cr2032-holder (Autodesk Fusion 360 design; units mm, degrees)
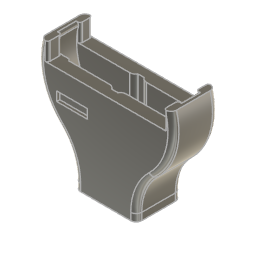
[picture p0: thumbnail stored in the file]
parameter "battery_diameter" = 20
parameter "battery_height" = 3.2
parameter "battery_negative_diameter" = 16
parameter "battery_negative_height" = 0.3
parameter "battery_tolerance" = 0.1
parameter "connector_width" = 2.9
parameter "connector_pin" = 1
parameter "holder_thickness_h" = 2
parameter "holder_thickness_w" = 2.05
parameter "pin_holder_distance" = 3
parameter "holder_clip" = 3
sketch "Sketch1" plane through (0, 0, 0) normal (0, 0, 1) x axis (1, 0, 0)
  line L1 (11.0748, -0.0744) -> (-11.0748, -0.0744)
  circle C1 centre (0, 0) radius 11.075
  circle C2 centre (0, 0) radius 10.05
  point P1 (0, 0)
  point P2 (0, 0)
  point P3 (0, 0)
  point P4 (-11.0748, -0.0744)
  point P5 (11.0748, -0.0744)
  coincident P1 P2
  coincident P1 P3
  coincident C1 P4
  coincident C1 P5
  horizontal L1
  dimension "d9" diameter C1 = 22.15 (= "battery_diameter + battery_tolerance + holder_thickness_w")
  dimension "d10" diameter C2 = 20.1 (= "battery_diameter + battery_tolerance")
extrude "Extrude1" new body sketch "Sketch1" no distance stored
extrude "Extrude2" add sketch "Sketch1" along normal blind 3.3 (= "battery_height + battery_tolerance")
sketch "Sketch2" plane through (0, 0, 3.3) normal (0, 0, 1) x axis (-1, 0, 0)
  line L1 (-10.0497, 0.0744) -> (-11.0748, 0.0744)
  line L2 (11.0748, 0.0744) -> (10.0497, 0.0744)
  line L3 (-11.0748, 0.0744) -> (11.0748, 0.0744)
  arc A1 centre (0, 0) radius 11.075 clockwise from (-11.0748, 0.0744) to (11.0748, 0.0744)
  arc A2 centre (0, 0) radius 10.05 clockwise from (-10.0497, 0.0744) to (10.0497, 0.0744)
  circle C1 centre (0, 0) radius 11.075
  point P2 (11.0748, 0.0744)
  point P8 (11.0748, 0.0744)
  point P3 (-11.0748, 0.0744)
  point P9 (-11.0748, 0.0744)
  concentric A1 C1
  coincident P2 P8
  coincident P3 P9
  dimension "d16" diameter C1 = 22.15 (= "battery_diameter + battery_tolerance + holder_thickness_w")
extrude "Extrude3" add sketch "Sketch2" along normal blind 2 (= "holder_thickness_h")
offset_faces "OffsetFaces1" distance 3 (= "holder_clip")
sketch "Sketch12" plane through (0, 0, 5.3) normal (0, 0, 1) x axis (-1, 0, 0)
  line L1 (10.6816, -2.9256) -> (-10.6816, -2.9256)
  line L2 (0, -5) -> (0, 0)
  line L3 (-9.5, 0) -> (0, 0)
  line L4 (-9.5, -3) -> (-9.5, 0)
  line L5 (0, -3) -> (-9.5, -3)
  line L6 (0, 0) -> (0, -3)
  line L7 (0, -3) -> (9.5, -3)
  line L8 (9.5, 0) -> (0, 0)
  line L9 (9.5, -3) -> (9.5, 0)
  arc A1 centre (0, 0) radius 11.075 clockwise from (-10.6816, -2.9256) to (10.6816, -2.9256)
  point P1 (0, 0)
  point P5 (0, 0)
  point P7 (0, 0)
  point P13 (0, 0)
  point P8 (-9.5, 0)
  point P14 (9.5, 0)
  point P9 (-9.5, -3)
  point P11 (9.5, -3)
  point P10 (0, -3)
  point P12 (0, -3)
  coincident P1 P5
  perpendicular L1 L2
  horizontal L3
  vertical L4
  horizontal L5
  vertical L6
  coincident P1 P7
  symmetric L2 P7 P13
  symmetric L2 P8 P14
  symmetric L2 P9 P11
  symmetric L2 P10 P12
  dimension "d112" distance P7 P8 = 9.5 (= "( battery_diameter / 2 ) - 0.5 mm")
  dimension "d113" distance P7 P10 = 3 (= "holder_clip")
extrude "Extrude15" cut sketch "Sketch12" profile of L1 L2 L3 L4 L6 L8 L9 to an object
sketch "Sketch3" plane through (0, 0, 5.3) normal (0, 0, 1) x axis (-1, 0, 0)
  line L1 (10.6816, -2.9256) -> (9.5, -2.9256)
  line L2 (5, 12.575) -> (-5, 12.575)
  line L3 (5, 9.575) -> (5, 12.575)
  line L4 (-5, 9.575) -> (5, 9.575)
  line L5 (-5, 12.575) -> (-5, 9.575)
  line L6 (5, 9.575) -> (-5, 12.575)
  line L7 (-5, 9.575) -> (5, 12.575)
  line L8 (-9.5, 0) -> (-9.5, -2.9256)
  line L9 (9.5, 0) -> (-9.5, 0)
  line L10 (9.5, -2.9256) -> (9.5, 0)
  line L11 (-9.5, -2.9256) -> (-10.6816, -2.9256)
  arc A1 centre (0, 0) radius 11.075 clockwise from (-10.6816, -2.9256) to (10.6816, -2.9256)
  point P9 (0, 11.075)
  point P7 (5, 9.575)
  point P8 (-5, 9.575)
  point P6 (5, 12.575)
  horizontal L2
  perpendicular L2 L3
  parallel L2 L4
  parallel L3 L5
  coincident L6 P9
  coincident L7 P9
  midpoint A1 P9
  dimension "d19" distance P7 P8 = 10
  dimension "d20" distance P6 P7 = 3
extrude "Extrude4" add sketch "Sketch3" profile of A1 L2 L3 L5 to an object
sketch "Sketch4" plane through (0, -12.575, 0) normal (0, -1, 0) x axis (1, 0, 0)
  line L1 (5, -2) -> (-5, -2)
  line L2 (5, 5.3) -> (5, -2)
  line L3 (-5, 5.3) -> (5, 5.3)
  line L4 (-5, -2) -> (-5, 5.3)
  line L5 (-1.4556, 1.85) -> (1.4444, 1.85)
  line L6 (-1.4556, 4.75) -> (-1.4556, 1.85)
  line L7 (1.4444, 4.75) -> (-1.4556, 4.75)
  line L8 (1.4444, 1.85) -> (1.4444, 4.75)
  line L9 (-1.4556, 4.75) -> (1.4444, 1.85)
  line L10 (1.4444, 4.75) -> (-1.4556, 1.85)
  line L11 (-1.4556, -1.45) -> (1.4444, -1.45)
  line L12 (-1.4556, 1.45) -> (-1.4556, -1.45)
  line L13 (1.4444, 1.45) -> (-1.4556, 1.45)
  line L14 (1.4444, -1.45) -> (1.4444, 1.45)
  line L15 (-1.4556, 1.45) -> (1.4444, -1.45)
  line L16 (1.4444, 1.45) -> (-1.4556, -1.45)
  point P10 (-0.0056, 3.3)
  point P15 (-0.0056, 0)
  point P8 (-1.4556, 4.75)
  point P9 (1.4444, 4.75)
  point P7 (-1.4556, 1.85)
  point P13 (-1.4556, 1.45)
  point P14 (1.4444, 1.45)
  point P12 (-1.4556, -1.45)
  horizontal L5
  perpendicular L5 L6
  parallel L5 L7
  parallel L6 L8
  coincident L9 P10
  coincident L10 P10
  horizontal L11
  perpendicular L11 L12
  parallel L11 L13
  parallel L12 L14
  coincident L15 P15
  coincident L16 P15
  dimension "d23" distance P8 P9 = 2.9 (= "connector_width")
  dimension "d24" distance P7 P8 = 2.9 (= "connector_width")
  dimension "d25" distance L3 P10 = 2 (= "holder_thickness_h")
  dimension "d26" distance P13 P14 = 2.9 (= "connector_width")
  dimension "d27" distance P12 P13 = 2.9 (= "connector_width")
  dimension "d28" distance L1 P15 = 2 (= "holder_thickness_h")
extrude "Extrude5" cut sketch "Sketch4" profile of L5 L6 L7 L8 L11 L12 L13 L14 to an object
sketch "Sketch5" plane through (0, 0, 0) normal (0, 0, 1) x axis (-1, 0, 0)
  line L1 (9.6147, -2.9256) -> (9.5, -2.9256)
  line L2 (0.5056, 10.05) -> (0.0056, 10.05)
  line L3 (0.5056, -2.25) -> (0.5056, 10.05)
  line L4 (0.0056, -2.25) -> (0.5056, -2.25)
  line L5 (0.0056, 10.05) -> (0.0056, -2.25)
  line L6 (-0.4944, 10.05) -> (0.0056, 10.05)
  line L7 (-0.4944, -2.25) -> (-0.4944, 10.05)
  line L8 (0.0056, -2.25) -> (-0.4944, -2.25)
  line L9 (0.0056, 10.05) -> (0.0056, -2.25)
  line L10 (9.5, -2.9256) -> (9.5, 0)
  line L11 (-9.5, -2.9256) -> (-9.6147, -2.9256)
  line L12 (-9.5, 0) -> (-9.5, -2.9256)
  line L13 (9.5, 0) -> (-9.5, 0)
  arc A1 centre (0, 0) radius 10.05 clockwise from (1.4556, 9.944) to (9.6147, -2.9256)
  arc A2 centre (0, 0) radius 10.05 clockwise from (-1.4444, 9.9457) to (1.4556, 9.944)
  arc A3 centre (0, 0) radius 10.05 clockwise from (-9.6147, -2.9256) to (-1.4444, 9.9457)
  point P7 (0.0056, 10.05)
  point P8 (0.5056, 10.05)
  horizontal L2
  vertical L3
  horizontal L4
  vertical L5
  midpoint A2 P7
  horizontal L6
  vertical L7
  horizontal L8
  vertical L9
  dimension "d31" distance P7 P8 = 0.5 (= "connector_pin / 2")
extrude "Extrude6" cut sketch "Sketch5" profile of A2 L1 L3 L5 L7 L9 against normal blind 0.5 (magnitude of "-connector_pin / 2")
sketch "Sketch6" plane through (0, 0, 3.3) normal (0, 0, -1) x axis (1, 0, 0)
  line L1 (9.6147, -2.9256) -> (9.5, -2.9256)
  line L2 (-0.5056, 10.05) -> (-0.0056, 10.05)
  line L3 (-0.5056, -2.3823) -> (-0.5056, 10.05)
  line L4 (-0.0056, -2.3823) -> (-0.5056, -2.3823)
  line L5 (-0.0056, 10.05) -> (-0.0056, -2.3823)
  line L6 (0.4944, 10.05) -> (-0.0056, 10.05)
  line L7 (0.4944, -2.3823) -> (0.4944, 10.05)
  line L8 (-0.0056, -2.3823) -> (0.4944, -2.3823)
  line L9 (-0.0056, 10.05) -> (-0.0056, -2.3823)
  line L10 (9.5, -2.9256) -> (9.5, 0)
  line L11 (-9.5, -2.9256) -> (-9.6147, -2.9256)
  line L12 (-9.5, 0) -> (-9.5, -2.9256)
  line L13 (9.5, 0) -> (-9.5, 0)
  arc A1 centre (0, 0) radius 10.05 clockwise from (1.4444, 9.9457) to (9.6147, -2.9256)
  arc A2 centre (0, 0) radius 10.05 clockwise from (-1.4556, 9.944) to (1.4444, 9.9457)
  arc A3 centre (0, 0) radius 10.05 clockwise from (-9.6147, -2.9256) to (-1.4556, 9.944)
  circle C1 centre (0, 0) radius 8.05
  point P1 (0, 0)
  point P7 (0, 0)
  point P8 (-0.0056, 10.05)
  point P9 (-0.5056, 10.05)
  coincident P1 P7
  horizontal L2
  vertical L3
  horizontal L4
  vertical L5
  midpoint A2 P8
  horizontal L6
  vertical L7
  horizontal L8
  vertical L9
  dimension "d34" diameter C1 = 16.1 (= "battery_negative_diameter + battery_tolerance")
  dimension "d35" distance P8 P9 = 0.5 (= "connector_pin / 2")
extrude "Extrude14" add sketch "Sketch6" profile of A1 A2 A3 L1 C1 L3 L7 along normal blind 0.3 (= "battery_negative_height")
extrude "Extrude8" cut sketch "Sketch6" profile of A2 L1 C1 L3 L4 L5 L7 L8 L9 against normal blind 0.5 (magnitude of "-connector_pin / 2")
fillet "Fillet7" radius 1 (= "connector_pin") 1 (= "connector_pin")
extrude "Extrude11" add of existing geometry blind 3 (= "pin_holder_distance")
fillet "Fillet10" radius 9 (= "pin_holder_distance * 3")
fillet "Fillet11" radius 0.7
fillet "Fillet16" radius 1.5
fillet "Fillet17" radius 1.25
fillet "Fillet18" radius 1.5
sketch "Sketch13" plane through (0, 0, -2) normal (0, 0, -1) x axis (1, 0, 0)
  line L1 (-9.5, 0) -> (-9.5, -2.9256)
  line L2 (9.5, 0) -> (-9.5, 0)
  line L3 (9.5, -2.9256) -> (9.5, 0)
  line L4 (10.6816, -2.9256) -> (9.5, -2.9256)
  line L5 (5, 15.575) -> (5, 14.3877)
  line L6 (-5, 15.575) -> (5, 15.575)
  line L7 (-5, 14.3877) -> (-5, 15.575)
  line L8 (-9.5, -2.9256) -> (-10.6816, -2.9256)
  line L9 (6.25, 6.5) -> (4.75, 6.5)
  line L10 (6.25, 1.5) -> (6.25, 6.5)
  line L11 (4.75, 1.5) -> (6.25, 1.5)
  line L12 (4.75, 6.5) -> (4.75, 1.5)
  line L13 (6.25, 1.5) -> (4.75, 6.5)
  line L14 (4.75, 1.5) -> (6.25, 6.5)
  line L15 (8, 4.75) -> (3, 4.75)
  line L16 (8, 3.25) -> (8, 4.75)
  line L17 (3, 3.25) -> (8, 3.25)
  line L18 (3, 4.75) -> (3, 3.25)
  line L19 (8, 3.25) -> (3, 4.75)
  line L20 (3, 3.25) -> (8, 4.75)
  arc A1 centre (0, 0) radius 11.075 clockwise from (7.7235, 7.9374) to (10.6816, -2.9256)
  arc A2 centre (14, 14.3877) radius 9 clockwise from (7.7235, 7.9374) to (5, 14.3877)
  arc A3 centre (-14, 14.3877) radius 9 clockwise from (-5, 14.3877) to (-7.7235, 7.9374)
  arc A4 centre (0, 0) radius 11.075 clockwise from (-10.6816, -2.9256) to (-7.7235, 7.9374)
  point P21 (5.5, 4)
  point P26 (5.5, 4)
  point P19 (6.25, 1.5)
  point P20 (4.75, 1.5)
  point P18 (6.25, 6.5)
  point P24 (8, 3.25)
  point P25 (3, 3.25)
  point P23 (8, 4.75)
  horizontal L9
  perpendicular L9 L10
  parallel L9 L11
  parallel L10 L12
  coincident L13 P21
  coincident L14 P21
  horizontal L15
  perpendicular L15 L16
  parallel L15 L17
  parallel L16 L18
  coincident L19 P26
  coincident L20 P26
  coincident P21 P26
  dimension "d122" distance P19 P20 = 1.5
  dimension "d123" distance P18 P19 = 5
  dimension "d124" distance P24 P25 = 5
  dimension "d125" distance P23 P24 = 1.5
  dimension "d126" distance L2 P26 = 4
  dimension "d127" distance L3 P21 = 4
sketch "Sketch14" plane through (0, 0, 5.3) normal (0, 0, 1) x axis (-1, 0, 0)
  line L1 (-9.5, 0) -> (-9.5, -2.9256)
  line L2 (9.5, 0) -> (-9.5, 0)
  line L3 (9.5, -2.9256) -> (9.5, 0)
  line L4 (10.6816, -2.9256) -> (9.5, -2.9256)
  line L5 (5, 15.575) -> (5, 14.3877)
  line L6 (-5, 15.575) -> (5, 15.575)
  line L7 (-5, 14.3877) -> (-5, 15.575)
  line L8 (-9.5, -2.9256) -> (-10.6816, -2.9256)
  line L9 (8, 4.75) -> (3, 4.75)
  line L10 (8, 3.25) -> (8, 4.75)
  line L11 (3, 3.25) -> (8, 3.25)
  line L12 (3, 4.75) -> (3, 3.25)
  line L13 (8, 3.25) -> (3, 4.75)
  line L14 (3, 3.25) -> (8, 4.75)
  arc A1 centre (0, 0) radius 11.075 clockwise from (7.7235, 7.9374) to (10.6816, -2.9256)
  arc A2 centre (14, 14.3877) radius 9 clockwise from (7.7235, 7.9374) to (5, 14.3877)
  arc A3 centre (-14, 14.3877) radius 9 clockwise from (-5, 14.3877) to (-7.7235, 7.9374)
  arc A4 centre (0, 0) radius 11.075 clockwise from (-10.6816, -2.9256) to (-7.7235, 7.9374)
  point P21 (5.5, 4)
  point P19 (8, 3.25)
  point P20 (3, 3.25)
  point P18 (8, 4.75)
  horizontal L9
  perpendicular L9 L10
  parallel L9 L11
  parallel L10 L12
  coincident L13 P21
  coincident L14 P21
  dimension "d128" distance P19 P20 = 5
  dimension "d129" distance P18 P19 = 1.5
  dimension "d130" distance L2 P21 = 4
  dimension "d131" distance L3 P21 = 4
extrude "Extrude16" cut sketch "Sketch14" profile of L9 L10 L11 L12 against normal blind 0.5
extrude "Extrude17" cut sketch "Sketch13" profile of L9 L10 L11 L12 L15 L16 L17 L18 against normal blind 0.5
fillet "Fillet22" radius 0.5
fillet "Fillet15" radius 0.9
fillet "Fillet19" radius 0.4
fillet "Fillet20" radius 0.4
fillet "Fillet21" radius 0.4
move "Move1" RotateAngle 90
sketch "Sketch15" plane through (0, 0, 0) normal (0, 0, 1) x axis (1, 0, 0)
  point P1 (0, 0)
  point P2 (0, 0)
  coincident P1 P2
move "Move2"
